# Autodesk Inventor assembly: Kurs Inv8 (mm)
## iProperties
Shininess: 64.0
Length Units: 11269
Angle Units: 11279
Time Units: 11290
Mass Units: 11283
Length Display Precision: 3
Angle Display Precision: 2
Compacted: True
Part Number: Kurs Inv8 (mm)
Document SubType Name: Assembly
Created: 2003-08
Designer: Administratör
Manufacturer: Standard
Standards Organization: Custom
Density: 0.0
Volumn: 0.0
Area: 0.0
PropertySet Name: Model Information
Control State: 0
Master: False
Checked Out: False
Author: Administratör
